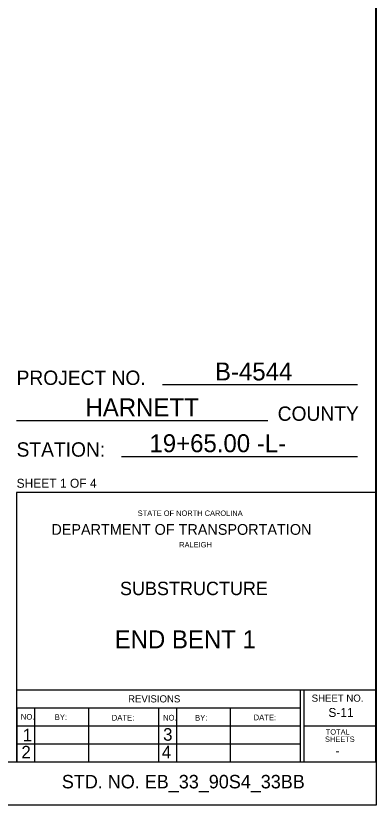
# Model space of a CAD drawing. Extents: x -41 to 251, y -169 to 237.
# Drawn here: x 64.22 to 75.71, y -50.47 to -25.28 of the extents above; entities that cross this region are included whole.
import ezdxf

# ---------------------------------------------------------------- set-up
doc = ezdxf.new("R2010")
doc.units = 0
for name, color, linetype in [('Plan Sheet CELL', 7, 'Continuous'), ('Plot Shape CELL', 7, 'Continuous'), ('Subtitle Text', 7, 'Continuous'), ('Text', 7, 'Continuous'), ('Title Text', 7, 'Continuous')]:
    doc.layers.add(name, color=color, linetype=linetype)

msp = doc.modelspace()

# ---------------------------------------------------------------- linework, layer by layer
at = {"layer": 'Plan Sheet CELL'}
for p, q in [((75.694, -0.989), (75.694, -49.079)), ((75.122, -37.056), (68.9, -37.056)), ((72.26, -38.201), (64.245, -38.201)), ((75.122, -39.345), (67.589, -39.345)), ((75.694, -40.49), (64.245, -40.49)), ((64.245, -40.49), (64.245, -49.079)), ((64.245, -46.788), (75.694, -46.788)), ((73.291, -46.788), (73.291, -49.079)), ((73.405, -46.788), (73.405, -49.079)), ((64.245, -47.36), (73.295, -47.36)), ((64.252, -47.36), (64.252, -49.079)), ((64.817, -47.36), (64.817, -49.079)), ((66.534, -47.37), (66.534, -49.087)), ((68.769, -47.36), (68.769, -49.093)), ((69.343, -47.36), (69.343, -49.08)), ((71.06, -47.36), (71.06, -49.08)), ((64.245, -47.933), (73.314, -47.933)), ((73.405, -47.933), (75.674, -47.933)), ((64.245, -48.505), (73.295, -48.505)), ((2.414, -49.079), (75.694, -49.079)), ((75.715, -50.467), (75.715, -50.467))]:
    msp.add_line(p, q, dxfattribs=at)
at = {"layer": 'Plot Shape CELL'}
msp.add_lwpolyline([(0, -0.087), (75.715, -0.087), (75.715, -50.467), (0, -50.467)], close=True, dxfattribs=at)

# ---------------------------------------------------------------- texts
at = {"layer": 'Plan Sheet CELL'}
for s, height, p in [('PROJECT NO.', 0.458, (64.245, -37.056)), ('COUNTY', 0.458, (72.572, -38.201)), ('STATION:', 0.458, (64.245, -39.345)), ('SHEET 1 OF 4', 0.28625, (64.245, -40.337)), ('STATE OF NORTH CAROLINA', 0.17174, (68.109, -41.235)), ('DEPARTMENT OF TRANSPORTATION', 0.34349, (65.355, -41.839)), ('RALEIGH', 0.1717, (69.431, -42.241)), ('REVISIONS', 0.229, (67.8, -47.187)), ('SHEET NO.', 0.229, (73.657, -47.165)), ('NO.', 0.1825, (64.381, -47.737)), ('BY:', 0.1825, (65.462, -47.746)), ('DATE:', 0.1825, (67.281, -47.766)), ('NO.', 0.1825, (68.915, -47.766)), ('BY:', 0.1825, (69.938, -47.767)), ('DATE:', 0.1825, (71.805, -47.756)), ('1', 0.401, (64.441, -48.428)), ('3', 0.401, (68.919, -48.409)), ('TOTAL', 0.1717, (74.106, -48.215)), ('SHEETS', 0.1717, (74.08, -48.447)), ('2', 0.401, (64.399, -48.973)), ('4', 0.401, (68.877, -48.973))]:
    msp.add_text(s, height=height, dxfattribs=at).set_placement(p)
at = {"layer": 'Subtitle Text'}
for s, p in [('SUBSTRUCTURE', (67.543, -43.764)), ('STD. NO. EB_33_90S4_33BB', (65.688, -49.929))]:
    msp.add_text(s, height=0.429, dxfattribs=at).set_placement(p)
at = {"layer": 'Text'}
for s, p in [('S-11', (74.189, -47.651)), ('-', (74.413, -48.873))]:
    msp.add_text(s, height=0.286, dxfattribs=at).set_placement(p)
at = {"layer": 'Title Text'}
for s, p in [('B-4544', (70.572, -36.913)), ('HARNETT', (66.442, -38.058)), ('19+65.00 -L-', (68.482, -39.202)), ('END BENT 1', (67.372, -45.46))]:
    msp.add_text(s, height=0.572, dxfattribs=at).set_placement(p)

doc.saveas('drawing.dxf')
